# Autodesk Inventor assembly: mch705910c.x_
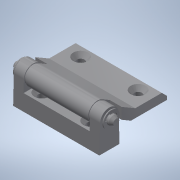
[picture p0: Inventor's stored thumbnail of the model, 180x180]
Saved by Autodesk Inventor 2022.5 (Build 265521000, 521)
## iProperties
Part Number: mch705910c.x_
Material: 一般
Document SubType Name: Assembly
Designer: ImaoCorp
Sending System: SOLIDWORKS 2017-2017317
MC: AMD64
MC_MODEL: Intel64 Family 6 Model 60 Stepping 3, GenuineIntel
OS: Windows_NT
FRU: Parasolid Version 29.0, build 201,  4-17-2017
FORMAT: text
GUISE: transmit
KEY: mch705910c
FILE: mch705910c.x_t
DATE: Fri Jul 26 11:41:55 2019
Author: ImaoCorp
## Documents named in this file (4)
- X:\14_SW2022-Inv2022\00_全2023-1023新製品(TCC)まで\m\mch705910c\MCH705910C.iam
- X:\14_SW2022-Inv2022\00_全2023-1023新製品(TCC)まで\m\mch705910c\mch705910c_01.ipt
- X:\14_SW2022-Inv2022\00_全2023-1023新製品(TCC)まで\m\mch705910c\mch705910c_02.ipt
- X:\14_SW2022-Inv2022\00_全2023-1023新製品(TCC)まで\m\mch705910c\mch705910c_03.ipt
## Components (3 placed, 3 different names)
1. mch705910c_01
2. mch705910c_02
3. mch705910c_03
